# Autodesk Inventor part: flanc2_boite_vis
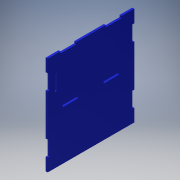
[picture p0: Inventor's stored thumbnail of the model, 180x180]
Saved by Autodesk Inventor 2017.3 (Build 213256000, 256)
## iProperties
Part Number: flanc2_boite_vis
Material: Générique
Document SubType Name: Modeling
Designer: ficho
Density: 1 g/cm^3
Appearance: Bleu - Peinture murale - Brillant
Author: ficho
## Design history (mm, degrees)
sketch "Esquisse1"
  geometry: L1 (91.3, 0)-(91.3, -3); L2 (91.3, -3)-(116, -3); L3 (116, -3)-(116, 0); L4 (44.7, 0)-(44.7, -3); L5 (44.7, -3)-(20, -3); L6 (20, -3)-(20, 0); L7 (116, 0)-(136, 0); L8 (0, 0)-(20, 0); L9 (44.7, 0)-(91.3, 0); L10 (136, -20)-(133, -20); L11 (133, -20)-(133, -44.7); L12 (133, -44.7)-(136, -44.7); L13 (136, -110.3)-(133, -110.3); L14 (133, -110.3)-(133, -135); L15 (133, -135)-(136, -135); L16 (136, -135)-(136, -155); L17 (136, 0)-(136, -20); L18 (136, -44.7)-(136, -110.3); L19 (0, -20)-(3, -20); L20 (3, -20)-(3, -44.7); L21 (3, -44.7)-(0, -44.7); L22 (0, -110.3)-(3, -110.3); L23 (3, -110.3)-(3, -135); L24 (3, -135)-(0, -135); L25 (0, -20)-(0, 0); L26 (0, -155)-(0, -135); L27 (0, -110.3)-(0, -44.7); L28 (136, -155)-(0, -155)
  constraints: 56 end point, 9 parallel, 8 horizontal, 7 perpendicular, 1 collinear, 1 point on line, 1 vertical
  dimensions: "d2" = 3 distance of L1.end L1.start; "d3" = 3 distance of L4.start L4.end; "d5" = 24.7 distance from line of L1.end L3; "d6" = 24.7 distance between parallel lines of L6 L4; "d12" = 3 distance of L12.end L11.end; "d13" = 24.7 distance of L11.end L10.end; "d14" = 3 distance of L15.end L14.end; "d15" = 24.7 distance of L14.end L13.end; "d16" = 20 distance between parallel lines of L10 L7; "d20" = 3 distance of L20.end L21.end; "d22" = 24.7 distance between parallel lines of L24 L22; "d23" = 24.7 distance between parallel lines of L21 L19; "d24" = 20 distance between parallel lines of L19 L8
extrude "Extrusion1" new body sketch "Esquisse1" distance "d25" = 3; taper "d26" = 0 deg
sketch "Esquisse2"
  geometry: L1 (51.65, 11.5)-(26.35, 11.5) reference; L2 (26.35, 14.5)-(51.65, 14.5) reference; L3 (75, 48.3)-(75, 23) reference; L4 (78, 48.3)-(78, 23) reference; L5 (75, 113)-(75, 87.7) reference; L6 (78, 113)-(78, 87.7) reference; L7 (75, 112.7)-(78, 112.7); L8 (78, 112.7)-(78, 88); L9 (78, 88)-(75, 88); L10 (75, 88)-(75, 112.7); L11 (75, 48)-(78, 48); L12 (78, 48)-(78, 23.3); L13 (78, 23.3)-(75, 23.3); L14 (75, 23.3)-(75, 48); L15 (26.65, 14.5)-(51.35, 14.5); L16 (51.35, 14.5)-(51.35, 11.5); L17 (51.35, 11.5)-(26.65, 11.5); L18 (26.65, 11.5)-(26.65, 14.5); 1 further point
  constraints: 24 end point, 6 parallel, 6 point on line, 3 horizontal, 3 perpendicular
  dimensions: "d27" = 0.3 distance from line of L16 L2.end; "d28" = 0.3 distance from line of L18 L2.start (= d27); "d29" = 0.3 distance from line of L11 L4.start (= d27); "d30" = 0.3 distance from line of L4.end L13 (= d29); "d31" = 0.3 distance from line of L7 L6.start (= d29); "d32" = 0.3 distance from line of L9 L6.end (= d31)
extrude "Extrusion2" cut sketch "Esquisse2" stored distance "d33" = 10; taper "d34" = 0 deg
node "Solide1"
node "Référence1"
node "Référence2"
node "Référence3"
node "Référence4"
node "Référence5"
node "Référence6"
other parameters: "d0" = 155, "d1" = 136, "d18" = 136, "d19" = 136
